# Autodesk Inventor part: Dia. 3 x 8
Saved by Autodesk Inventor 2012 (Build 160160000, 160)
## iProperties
Created: 2012-11
Part Number: Dia. 3 x 8
Material: Default
Document SubType Name: Modeling
Designer: Administrateur
Density: 1 g/cm^3
Title: Rondelle plate Dia. 3 x 12
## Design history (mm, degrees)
node "Dia. 3 x 81"
node "Dia. 3 x 8"
node "Base1"
